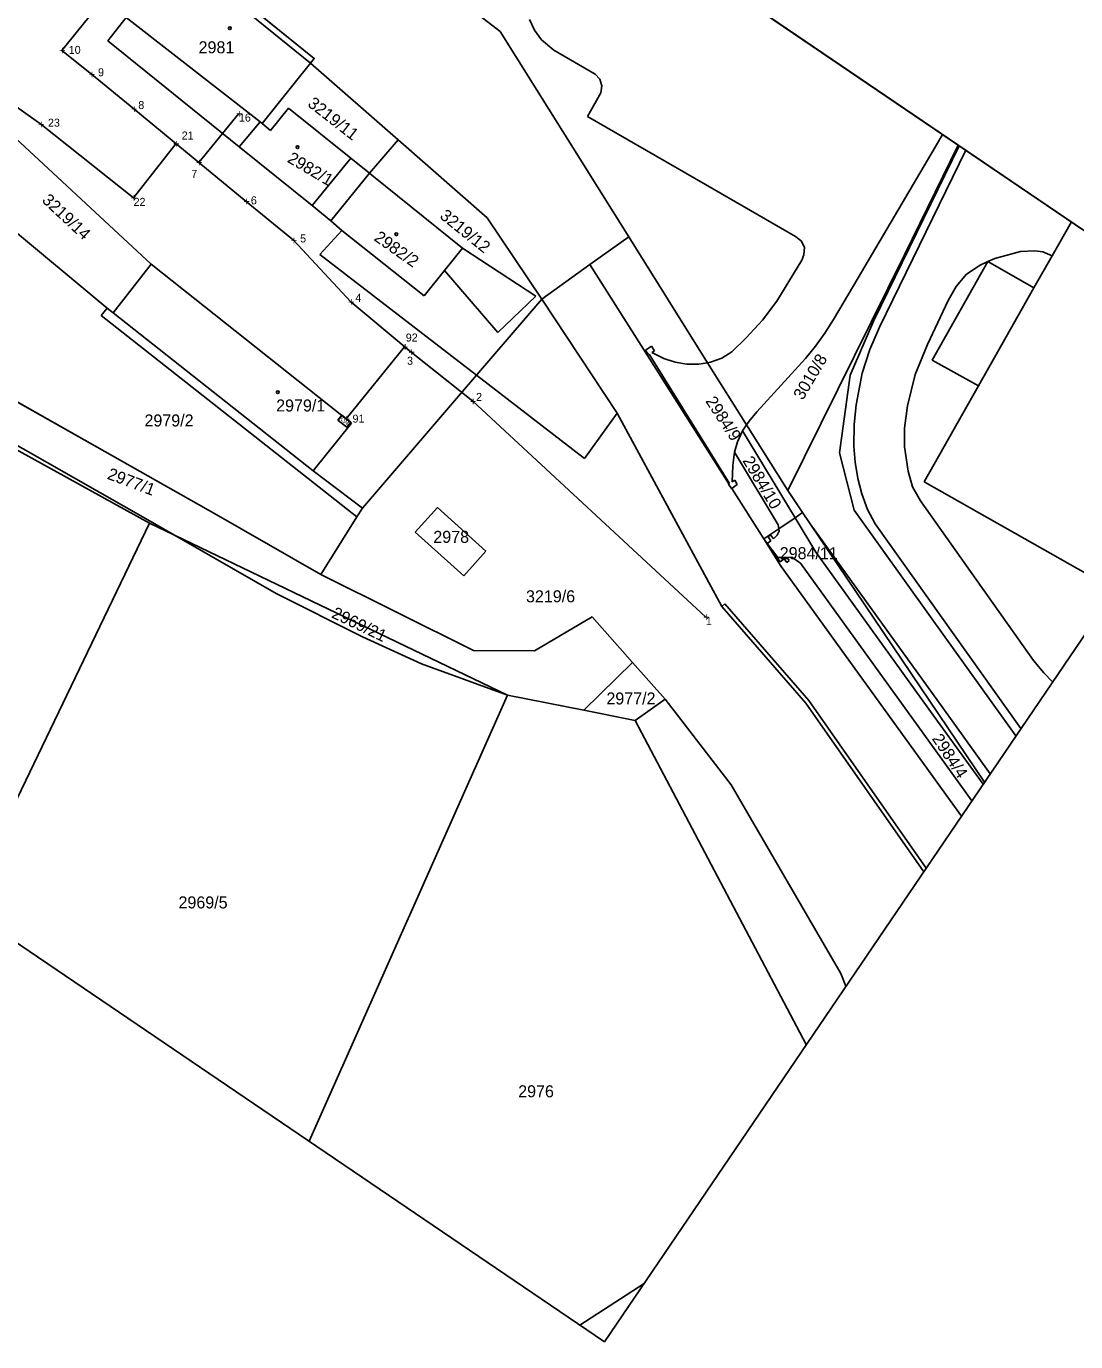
# Model space of a CAD drawing. Extents: x -621058 to -620023, y -1122866 to -1122030.
# Drawn here: x -620261.7 to -620130.6, y -1122865.7 to -1122701.3 of the extents above; entities that cross this region are included whole.
import ezdxf

# ---------------------------------------------------------------- set-up
doc = ezdxf.new("R2010")
doc.units = 0
for name, color, linetype in [('060604_ROZVODY_SEE', 7, 'Continuous'), ('BODY', 7, 'Continuous'), ('BODY POPIS', 7, 'Continuous'), ('RÁMY', 7, 'Continuous'), ('UZEMNĚNÍ', 7, 'Continuous'), ('Vrstva 53', 7, 'Continuous'), ('Vrstva 55', 7, 'Continuous'), ('Vrstva 56', 7, 'Continuous'), ('Vrstva 57', 7, 'Continuous')]:
    doc.layers.add(name, color=color, linetype=linetype)

msp = doc.modelspace()

# ---------------------------------------------------------------- linework, layer by layer
at = {"layer": '060604_ROZVODY_SEE'}
for p, q in [((-620235.16, -1122712.24), (-620240.17, -1122718.34)), ((-620221.75, -1122750.37), (-620214.46, -1122741.38))]:
    msp.add_line(p, q, dxfattribs=at)
for points in [[(-620243.03, -1122716), (-620248.32, -1122722.77), (-620259.89, -1122713.57), (-620277.71, -1122700.9), (-620282.35, -1122705.3), (-620297.82, -1122689.49), (-620304.22, -1122684.86), (-620310.82, -1122680.06), (-620316.82, -1122675.99), (-620322.23, -1122672.32), (-620326.63, -1122669.41), (-620343.18, -1122658.46), (-620368.5, -1122642.9), (-620411.56, -1122614.92), (-620424.16, -1122607.09), (-620443.53, -1122595), (-620444.24, -1122596.15)], [(-620176.84, -1122775.14), (-620205.95, -1122748.19), (-620213.63, -1122742.04), (-620221.17, -1122735.76), (-620228.34, -1122728.07), (-620234.26, -1122723.21), (-620240.17, -1122718.34), (-620248.3, -1122711.66), (-620253.57, -1122707.33), (-620257.27, -1122704.36), (-620247.33, -1122692.03), (-620244.52, -1122694.3)]]:
    msp.add_lwpolyline(points, dxfattribs=at)
msp.add_lwpolyline([(-620222.31, -1122749.92), (-620221.19, -1122750.81), (-620221.68, -1122751.43), (-620222.79, -1122750.54)], close=True, dxfattribs=at)
at = {"layer": 'RÁMY'}
for points in [[(-620974.7, -1122152.91), (-620106.07, -1122742.82), (-620189.51, -1122865.67), (-621058.13, -1122275.76)], [(-620887.83, -1122211.9), (-620106.07, -1122742.82), (-620189.51, -1122865.67), (-620971.26, -1122334.75)], [(-620109.51, -1122560.98), (-620022.64, -1122619.97), (-620106.07, -1122742.82), (-620192.94, -1122683.83)]]:
    msp.add_lwpolyline(points, close=True, dxfattribs=at)
at = {"layer": 'UZEMNĚNÍ'}
msp.add_lwpolyline([(-620221.75, -1122750.37), (-620214.46, -1122741.38), (-620205.95, -1122748.19), (-620176.84, -1122775.14)], dxfattribs=at)
at = {"layer": 'Vrstva 53'}
for p, q in [((-620226.24, -1122705.93), (-620243.01, -1122692.32)), ((-620251.53, -1122703.16), (-620249.26, -1122700.23)), ((-620278.07, -1122701.42), (-620246.12, -1122731.05)), ((-620235.14, -1122716.41), (-620251.53, -1122703.16)), ((-620226.24, -1122705.93), (-620228.28, -1122708.48)), ((-620226.24, -1122705.93), (-620215.29, -1122715.52)), ((-620228.28, -1122708.48), (-620232.27, -1122713.47)), ((-620231.2, -1122714.35), (-620228.95, -1122711.56)), ((-620228.95, -1122711.56), (-620221.19, -1122717.82)), ((-620232.51, -1122713.28), (-620235.14, -1122716.41)), ((-620232.27, -1122713.47), (-620232.51, -1122713.28)), ((-620232.27, -1122713.47), (-620231.2, -1122714.35)), ((-620226.02, -1122723.74), (-620235.14, -1122716.41)), ((-620218.86, -1122719.7), (-620215.29, -1122715.52)), ((-620221.19, -1122717.82), (-620218.86, -1122719.7)), ((-620218.86, -1122719.7), (-620223.68, -1122725.62)), ((-620226.02, -1122723.74), (-620223.68, -1122725.62)), ((-620251.62, -1122736.54), (-620264.06, -1122726.18)), ((-620223.68, -1122725.62), (-620222.3, -1122726.83)), ((-620222.3, -1122726.83), (-620225.04, -1122729.85)), ((-620225.04, -1122729.85), (-620205.48, -1122744.93)), ((-620250.89, -1122737.15), (-620246.12, -1122731.05)), ((-620246.12, -1122731.05), (-620221.1, -1122750.9)), ((-620205.48, -1122744.93), (-620197.33, -1122735.44)), ((-620197.33, -1122735.44), (-620187.9, -1122749.66)), ((-620252.35, -1122737.47), (-620251.62, -1122736.54)), ((-620220.43, -1122762.64), (-620252.35, -1122737.47)), ((-620250.89, -1122737.15), (-620251.62, -1122736.54)), ((-620251.9, -1122754.44), (-620275.74, -1122741.01)), ((-620205.48, -1122744.93), (-620219.74, -1122761.53)), ((-620187.9, -1122749.66), (-620174.83, -1122773.82)), ((-620221.1, -1122750.9), (-620225.88, -1122756.88)), ((-620238, -1122762.33), (-620251.9, -1122754.44)), ((-620225.88, -1122756.88), (-620219.74, -1122761.53)), ((-620224.92, -1122769.84), (-620238, -1122762.33)), ((-620220.43, -1122762.64), (-620224.92, -1122769.84)), ((-620219.74, -1122761.53), (-620220.43, -1122762.64)), ((-620213.13, -1122764.54), (-620210.34, -1122761.46)), ((-620210.34, -1122761.46), (-620204.3, -1122766.9)), ((-620207.05, -1122769.98), (-620213.13, -1122764.54)), ((-620204.3, -1122766.9), (-620207.05, -1122769.98)), ((-620205.84, -1122779.33), (-620224.92, -1122769.84)), ((-620174.83, -1122773.82), (-620164.34, -1122785.91)), ((-620191.03, -1122775.11), (-620198.25, -1122779.35)), ((-620185.98, -1122780.81), (-620191.03, -1122775.11)), ((-620198.25, -1122779.35), (-620205.84, -1122779.33)), ((-620185.98, -1122780.81), (-620181.92, -1122785.4)), ((-620173.68, -1122796.12), (-620181.92, -1122785.4)), ((-620164.34, -1122785.91), (-620149.63, -1122806.95)), ((-620159.98, -1122819.68), (-620173.68, -1122796.12)), ((-620159.34, -1122821.26), (-620159.98, -1122819.68))]:
    msp.add_line(p, q, dxfattribs=at)
msp.add_lwpolyline([(-620242.51, -1122691.82), (-620225.75, -1122705.35), (-620226.24, -1122705.93)], dxfattribs=at)
at = {"layer": 'Vrstva 55'}
for p, q in [((-620243.36, -1122670.23), (-620202.54, -1122702)), ((-620225.75, -1122705.35), (-620242.51, -1122691.82)), ((-620243.01, -1122692.32), (-620226.24, -1122705.93)), ((-620251.53, -1122703.16), (-620249.26, -1122700.23)), ((-620246.12, -1122731.05), (-620278.07, -1122701.42)), ((-620202.54, -1122702), (-620186.47, -1122727.64)), ((-620198.25, -1122701.83), (-620198.88, -1122700.47)), ((-620197.37, -1122703.03), (-620198.25, -1122701.83)), ((-620235.14, -1122716.41), (-620251.53, -1122703.16)), ((-620195.84, -1122704.31), (-620197.37, -1122703.03)), ((-620190.67, -1122707.32), (-620195.84, -1122704.31)), ((-620226.24, -1122705.93), (-620228.28, -1122708.48)), ((-620225.75, -1122705.35), (-620226.24, -1122705.93)), ((-620215.29, -1122715.52), (-620226.24, -1122705.93)), ((-620228.28, -1122708.48), (-620232.27, -1122713.47)), ((-620190.09, -1122707.94), (-620190.67, -1122707.32)), ((-620189.82, -1122708.78), (-620190.09, -1122707.94)), ((-620191.6, -1122712.59), (-620189.94, -1122709.65)), ((-620189.94, -1122709.65), (-620189.82, -1122708.78)), ((-620231.2, -1122714.35), (-620228.95, -1122711.56)), ((-620228.95, -1122711.56), (-620221.19, -1122717.82)), ((-620232.51, -1122713.28), (-620235.14, -1122716.41)), ((-620232.27, -1122713.47), (-620232.51, -1122713.28)), ((-620232.27, -1122713.47), (-620231.2, -1122714.35)), ((-620176.88, -1122721.09), (-620191.6, -1122712.59)), ((-620147.27, -1122714.85), (-620148.19, -1122716.42)), ((-620235.14, -1122716.41), (-620226.02, -1122723.74)), ((-620218.86, -1122719.7), (-620215.29, -1122715.52)), ((-620204.16, -1122725.27), (-620215.29, -1122715.52)), ((-620148.19, -1122716.42), (-620158.35, -1122733.67)), ((-620155.87, -1122738.11), (-620145.18, -1122716.27)), ((-620152.03, -1122729.88), (-620145.31, -1122716.18)), ((-620221.19, -1122717.82), (-620218.86, -1122719.7)), ((-620223.68, -1122725.62), (-620218.86, -1122719.7)), ((-620218.86, -1122719.7), (-620218.55, -1122719.95)), ((-620218.55, -1122719.95), (-620207.24, -1122729.07)), ((-620165.63, -1122727.6), (-620176.88, -1122721.09)), ((-620226.02, -1122723.74), (-620223.68, -1122725.62)), ((-620251.62, -1122736.54), (-620264.06, -1122726.18)), ((-620223.68, -1122725.62), (-620222.3, -1122726.83)), ((-620197.33, -1122735.44), (-620204.16, -1122725.27)), ((-620132.92, -1122728.86), (-620131.17, -1122725.78)), ((-620222.3, -1122726.83), (-620225.04, -1122729.85)), ((-620222.3, -1122726.83), (-620212.02, -1122735)), ((-620186.47, -1122727.64), (-620191.31, -1122731.11)), ((-620186.47, -1122727.64), (-620176.62, -1122743.36)), ((-620164.91, -1122728.17), (-620165.63, -1122727.6)), ((-620164.53, -1122728.99), (-620164.91, -1122728.17)), ((-620225.04, -1122729.85), (-620205.48, -1122744.93)), ((-620198.09, -1122735.05), (-620207.24, -1122729.07)), ((-620152.03, -1122729.88), (-620166.6, -1122759.34)), ((-620164.86, -1122730.54), (-620164.6, -1122729.87)), ((-620164.6, -1122729.87), (-620164.53, -1122728.99)), ((-620133.58, -1122730.02), (-620132.92, -1122728.86)), ((-620250.89, -1122737.15), (-620246.12, -1122731.05)), ((-620246.12, -1122731.05), (-620221.1, -1122750.9)), ((-620191.31, -1122731.11), (-620197.33, -1122735.44)), ((-620167.98, -1122735.66), (-620164.86, -1122730.54)), ((-620148.58, -1122743.04), (-620141.6, -1122730.74)), ((-620141.6, -1122730.74), (-620135.85, -1122734.02)), ((-620135.85, -1122734.02), (-620133.58, -1122730.02)), ((-620212.02, -1122735), (-620209.48, -1122731.85)), ((-620209.48, -1122731.85), (-620202.82, -1122739.59)), ((-620158.35, -1122733.67), (-620160.91, -1122737.97)), ((-620205.48, -1122744.93), (-620197.33, -1122735.44)), ((-620202.82, -1122739.59), (-620198.09, -1122735.05)), ((-620187.9, -1122749.66), (-620197.33, -1122735.44)), ((-620169.77, -1122738.05), (-620167.98, -1122735.66)), ((-620252.35, -1122737.47), (-620251.62, -1122736.54)), ((-620220.43, -1122762.64), (-620252.35, -1122737.47)), ((-620250.89, -1122737.15), (-620251.62, -1122736.54)), ((-620171.8, -1122740.25), (-620169.77, -1122738.05)), ((-620160.91, -1122737.97), (-620161.97, -1122739.66)), ((-620158.82, -1122744.94), (-620155.87, -1122738.11)), ((-620161.97, -1122739.66), (-620163.14, -1122741.3)), ((-620275.74, -1122741.01), (-620251.9, -1122754.44)), ((-620183.63, -1122741.31), (-620184.39, -1122741.79)), ((-620183.27, -1122741.89), (-620183.63, -1122741.31)), ((-620173.6, -1122742), (-620171.8, -1122740.25)), ((-620163.14, -1122741.3), (-620164.41, -1122742.85)), ((-620184.39, -1122741.79), (-620184.05, -1122742.35)), ((-620184.05, -1122742.35), (-620183.92, -1122742.28)), ((-620183.92, -1122742.28), (-620173.87, -1122758.44)), ((-620183.57, -1122742.07), (-620183.27, -1122741.89)), ((-620182.08, -1122742.82), (-620183.57, -1122742.07)), ((-620180.68, -1122743.31), (-620182.08, -1122742.82)), ((-620176.26, -1122743.3), (-620174.86, -1122742.79)), ((-620174.86, -1122742.79), (-620173.6, -1122742)), ((-620164.41, -1122742.85), (-620170.46, -1122749.51)), ((-620142.8, -1122746.27), (-620148.58, -1122743.04)), ((-620280.66, -1122744.45), (-620246.32, -1122763.41)), ((-620280.18, -1122743.84), (-620246.23, -1122763.17)), ((-620179.21, -1122743.55), (-620180.68, -1122743.31)), ((-620177.73, -1122743.55), (-620179.21, -1122743.55)), ((-620176.62, -1122743.36), (-620177.73, -1122743.55)), ((-620176.62, -1122743.36), (-620176.26, -1122743.3)), ((-620176.62, -1122743.36), (-620171.74, -1122751.13)), ((-620205.48, -1122744.93), (-620219.74, -1122761.53)), ((-620160.13, -1122754.62), (-620158.82, -1122744.94)), ((-620149.58, -1122758.23), (-620142.8, -1122746.27)), ((-620174.83, -1122773.82), (-620187.9, -1122749.66)), ((-620170.46, -1122749.51), (-620171.42, -1122750.65)), ((-620221.1, -1122750.9), (-620225.88, -1122756.88)), ((-620172.25, -1122751.89), (-620171.74, -1122751.13)), ((-620171.42, -1122750.65), (-620171.74, -1122751.13)), ((-620171.74, -1122751.13), (-620166.6, -1122759.34)), ((-620172.87, -1122753.23), (-620172.25, -1122751.89)), ((-620251.9, -1122754.44), (-620238, -1122762.33)), ((-620173.48, -1122756.2), (-620173.24, -1122754.52)), ((-620173.24, -1122754.52), (-620172.87, -1122753.23)), ((-620173.24, -1122754.52), (-620167.81, -1122763.6)), ((-620173.53, -1122758.23), (-620173.48, -1122756.2)), ((-620158.3, -1122761.8), (-620160.13, -1122754.62)), ((-620225.88, -1122756.88), (-620219.74, -1122761.53)), ((-620173.96, -1122758.5), (-620174, -1122758.53)), ((-620174, -1122758.53), (-620173.64, -1122759.08)), ((-620173.87, -1122758.44), (-620173.96, -1122758.5)), ((-620173.64, -1122759.08), (-620173.61, -1122759.06)), ((-620173.61, -1122759.06), (-620172.91, -1122758.59)), ((-620173.22, -1122758.03), (-620173.53, -1122758.23)), ((-620172.91, -1122758.59), (-620173.22, -1122758.03)), ((-620166.6, -1122759.34), (-620164.75, -1122762.08)), ((-620125.72, -1122771.75), (-620149.58, -1122758.23)), ((-620238, -1122762.33), (-620224.92, -1122769.84)), ((-620220.43, -1122762.64), (-620224.92, -1122769.84)), ((-620219.74, -1122761.53), (-620220.43, -1122762.64)), ((-620213.13, -1122764.54), (-620210.34, -1122761.46)), ((-620210.34, -1122761.46), (-620204.3, -1122766.9)), ((-620165.7, -1122762.73), (-620167.73, -1122764.1)), ((-620164.75, -1122762.08), (-620165.7, -1122762.73)), ((-620164.75, -1122762.08), (-620163.81, -1122763.48)), ((-620148.77, -1122775.1), (-620158.3, -1122761.8)), ((-620246.32, -1122763.41), (-620267.15, -1122806.71)), ((-620246.32, -1122763.41), (-620243.2, -1122764.91)), ((-620246.23, -1122763.17), (-620243.2, -1122764.91)), ((-620167.73, -1122764.1), (-620169.61, -1122765.37)), ((-620167.81, -1122763.6), (-620167.73, -1122764.1)), ((-620163.81, -1122763.48), (-620142.03, -1122795.76)), ((-620147.22, -1122786.5), (-620163.81, -1122763.48)), ((-620243.2, -1122764.91), (-620230.53, -1122772.18)), ((-620243.2, -1122764.91), (-620201.6, -1122784.9)), ((-620207.05, -1122769.98), (-620213.13, -1122764.54)), ((-620169.61, -1122765.37), (-620169.18, -1122765.95)), ((-620169.18, -1122765.95), (-620167.55, -1122768.23)), ((-620169.18, -1122765.95), (-620167.86, -1122767.72)), ((-620204.3, -1122766.9), (-620207.05, -1122769.98)), ((-620167.86, -1122767.72), (-620166.7, -1122767.69)), ((-620166.7, -1122767.69), (-620166.09, -1122767.67)), ((-620166.41, -1122768.09), (-620166.7, -1122767.69)), ((-620166.09, -1122767.67), (-620165.02, -1122768.39)), ((-620167.55, -1122768.23), (-620167.06, -1122767.87)), ((-620167.06, -1122767.87), (-620166.72, -1122768.33)), ((-620166.72, -1122768.33), (-620166.41, -1122768.09)), ((-620165.02, -1122768.39), (-620150.35, -1122788.75)), ((-620224.92, -1122769.84), (-620205.84, -1122779.33)), ((-620219.74, -1122777.62), (-620230.53, -1122772.18)), ((-620164.34, -1122785.91), (-620174.83, -1122773.82)), ((-620198.25, -1122779.35), (-620191.03, -1122775.11)), ((-620191.03, -1122775.11), (-620185.98, -1122780.81)), ((-620138.1, -1122789.98), (-620148.77, -1122775.1)), ((-620212.35, -1122780.98), (-620219.74, -1122777.62)), ((-620205.84, -1122779.33), (-620198.25, -1122779.35)), ((-620192.09, -1122786.79), (-620185.98, -1122780.81)), ((-620185.98, -1122780.81), (-620181.92, -1122785.4)), ((-620201.6, -1122784.9), (-620212.35, -1122780.98)), ((-620201.6, -1122784.9), (-620226.38, -1122840.63)), ((-620192.09, -1122786.79), (-620201.6, -1122784.9)), ((-620181.92, -1122785.4), (-620185.65, -1122788.07)), ((-620181.92, -1122785.4), (-620173.68, -1122796.12)), ((-620185.65, -1122788.07), (-620192.09, -1122786.79)), ((-620149.63, -1122806.95), (-620164.34, -1122785.91)), ((-620141.32, -1122794.73), (-620147.22, -1122786.5)), ((-620150.35, -1122788.75), (-620143.6, -1122798.08)), ((-620173.68, -1122796.12), (-620159.98, -1122819.68)), ((-620159.98, -1122819.68), (-620159.34, -1122821.26)), ((-620184.56, -1122858.39), (-620192.57, -1122863.59))]:
    msp.add_line(p, q, dxfattribs=at)
at = {"layer": 'Vrstva 56'}
for p, q in [((-620249.26, -1122700.23), (-620232.51, -1122713.28)), ((-620226.02, -1122723.74), (-620221.19, -1122717.82)), ((-620144.36, -1122716.82), (-620155.13, -1122738.93)), ((-620209.48, -1122731.85), (-620207.24, -1122729.07)), ((-620140.72, -1122730.36), (-620137.55, -1122729.49)), ((-620137.55, -1122729.49), (-620135.75, -1122729.37)), ((-620135.75, -1122729.37), (-620134.75, -1122729.52)), ((-620134.75, -1122729.52), (-620133.58, -1122730.02)), ((-620191.31, -1122731.11), (-620173.96, -1122758.5)), ((-620144.26, -1122732.31), (-620142.59, -1122731.16)), ((-620142.59, -1122731.16), (-620141.6, -1122730.74)), ((-620141.6, -1122730.74), (-620140.72, -1122730.36)), ((-620145.58, -1122733.83), (-620144.26, -1122732.31)), ((-620146.56, -1122735.6), (-620145.58, -1122733.83)), ((-620142.8, -1122746.27), (-620135.85, -1122734.02)), ((-620149.15, -1122741.1), (-620146.56, -1122735.6)), ((-620225.88, -1122756.88), (-620250.89, -1122737.15)), ((-620156.36, -1122741.72), (-620155.13, -1122738.93)), ((-620150.71, -1122744.84), (-620149.15, -1122741.1)), ((-620157.32, -1122744.66), (-620156.36, -1122741.72)), ((-620158.07, -1122748.62), (-620157.32, -1122744.66)), ((-620205.48, -1122744.93), (-620191.99, -1122755.33)), ((-620151.67, -1122748.77), (-620150.71, -1122744.84)), ((-620191.99, -1122755.33), (-620187.9, -1122749.66)), ((-620158.33, -1122751.09), (-620158.07, -1122748.62)), ((-620152.03, -1122751.56), (-620151.67, -1122748.77)), ((-620158.37, -1122753.78), (-620158.33, -1122751.09)), ((-620172.25, -1122751.89), (-620165.7, -1122762.73)), ((-620152.03, -1122753.86), (-620152.03, -1122751.56)), ((-620158.2, -1122755.8), (-620158.37, -1122753.78)), ((-620151.58, -1122756.91), (-620152.03, -1122753.86)), ((-620157.86, -1122757.82), (-620158.2, -1122755.8)), ((-620157.34, -1122759.76), (-620157.86, -1122757.82)), ((-620151.04, -1122758.86), (-620151.58, -1122756.91)), ((-620173.61, -1122759.06), (-620169.61, -1122765.37)), ((-620150.03, -1122760.6), (-620151.04, -1122758.86)), ((-620156.64, -1122761.69), (-620157.34, -1122759.76)), ((-620135.93, -1122780.56), (-620150.03, -1122760.6)), ((-620165.7, -1122762.73), (-620163.11, -1122767.02)), ((-620155.67, -1122763.48), (-620156.64, -1122761.69)), ((-620167.68, -1122764.39), (-620167.95, -1122764.93)), ((-620167.73, -1122764.1), (-620167.68, -1122764.39)), ((-620137.49, -1122789.08), (-620155.67, -1122763.48)), ((-620169.61, -1122765.37), (-620167.41, -1122768.84)), ((-620168.7, -1122765.62), (-620169.18, -1122765.95)), ((-620168.75, -1122764.87), (-620169.05, -1122765.1)), ((-620169.05, -1122765.1), (-620168.7, -1122765.62)), ((-620168.38, -1122765.37), (-620168.75, -1122764.87)), ((-620167.95, -1122764.93), (-620168.38, -1122765.37)), ((-620163.11, -1122767.02), (-620148.44, -1122787.38)), ((-620167.41, -1122768.84), (-620144.9, -1122800)), ((-620174.83, -1122773.82), (-620174.45, -1122773.49)), ((-620174.45, -1122773.49), (-620163.96, -1122785.58)), ((-620134.64, -1122782.1), (-620135.93, -1122780.56)), ((-620133.52, -1122783.24), (-620134.64, -1122782.1)), ((-620163.96, -1122785.58), (-620149.33, -1122806.51)), ((-620148.44, -1122787.38), (-620142.2, -1122796.02)), ((-620185.65, -1122788.07), (-620164.29, -1122828.54))]:
    msp.add_line(p, q, dxfattribs=at)
at = {"layer": 'Vrstva 57'}
for centre in [(-620236.29, -1122701.58), (-620227.84, -1122716.43), (-620215.5, -1122727.32), (-620230.31, -1122747.04)]:
    msp.add_circle(centre, 0.175, dxfattribs=at)

# ---------------------------------------------------------------- texts
at = {"layer": '060604_ROZVODY_SEE'}
msp.add_text('KS4', height=0.5, rotation=321.5727, dxfattribs=at).set_placement((-620222.66, -1122750.4))
at = {"layer": 'BODY'}
for p in [(-620257.6, -1122704.86), (-620253.9, -1122707.83), (-620248.63, -1122712.16), (-620260.22, -1122714.07), (-620235.49, -1122712.74), (-620243.36, -1122716.5), (-620240.51, -1122718.84), (-620248.65, -1122723.27), (-620234.59, -1122723.71), (-620228.67, -1122728.57), (-620221.5, -1122736.26), (-620214.79, -1122741.88), (-620213.97, -1122742.54), (-620206.29, -1122748.69), (-620222.08, -1122750.87), (-620177.18, -1122775.64)]:
    msp.add_text('+', height=1, dxfattribs=at).set_placement(p)
at = {"layer": 'BODY POPIS'}
for s, p in [('10', (-620256.42, -1122704.78)), ('9', (-620252.76, -1122707.58)), ('8', (-620247.73, -1122711.67)), ('23', (-620259.01, -1122713.88)), ('16', (-620235.16, -1122713.24)), ('21', (-620242.31, -1122715.48)), ('7', (-620241.11, -1122720.28)), ('22', (-620248.32, -1122723.77)), ('6', (-620233.67, -1122723.58)), ('5', (-620227.52, -1122728.34)), ('4', (-620220.62, -1122735.76)), ('92', (-620214.32, -1122740.72)), ('3', (-620214.16, -1122743.62)), ('2', (-620205.54, -1122748.14)), ('91', (-620220.97, -1122750.85)), ('1', (-620176.84, -1122776.14))]:
    msp.add_text(s, height=1, dxfattribs=at).set_placement(p)
at = {"layer": 'Vrstva 57'}
for s, p in [('2981', (-620240.2, -1122704.71)), ('2979/1', (-620230.51, -1122749.46)), ('2979/2', (-620246.96, -1122751.33)), ('2978', (-620210.88, -1122765.87)), ('2984/11', (-620167.61, -1122767.91)), ('3219/6', (-620199.3, -1122773.3)), ('2977/2', (-620189.26, -1122786.06)), ('2969/5', (-620242.71, -1122811.54)), ('2976', (-620200.28, -1122835.14))]:
    msp.add_text(s, height=1.5, dxfattribs=at).set_placement(p)
for s, rotation, p in [('3219/11', 322.1138, (-620226.69, -1122711.22)), ('2982/1', 329.4, (-620229.23, -1122718.23)), ('3219/14', 316.8, (-620259.86, -1122723.19)), ('3219/12', 321.2409, (-620210.18, -1122725.22)), ('2982/2', 324.9, (-620218.4, -1122728.01)), ('3010/8', 59.4683, (-620164.72, -1122748.13)), ('2984/9', 303.103, (-620176.94, -1122748.16)), ('2984/10', 300.8806, (-620172.31, -1122755.59)), ('2977/1', 339.3, (-620251.72, -1122757.84)), ('2969/21', 334.3112, (-620223.7, -1122775.15)), ('2984/4', 303.3, (-620148.65, -1122790.32))]:
    msp.add_text(s, height=1.5, rotation=rotation, dxfattribs=at).set_placement(p)

doc.saveas('drawing.dxf')
